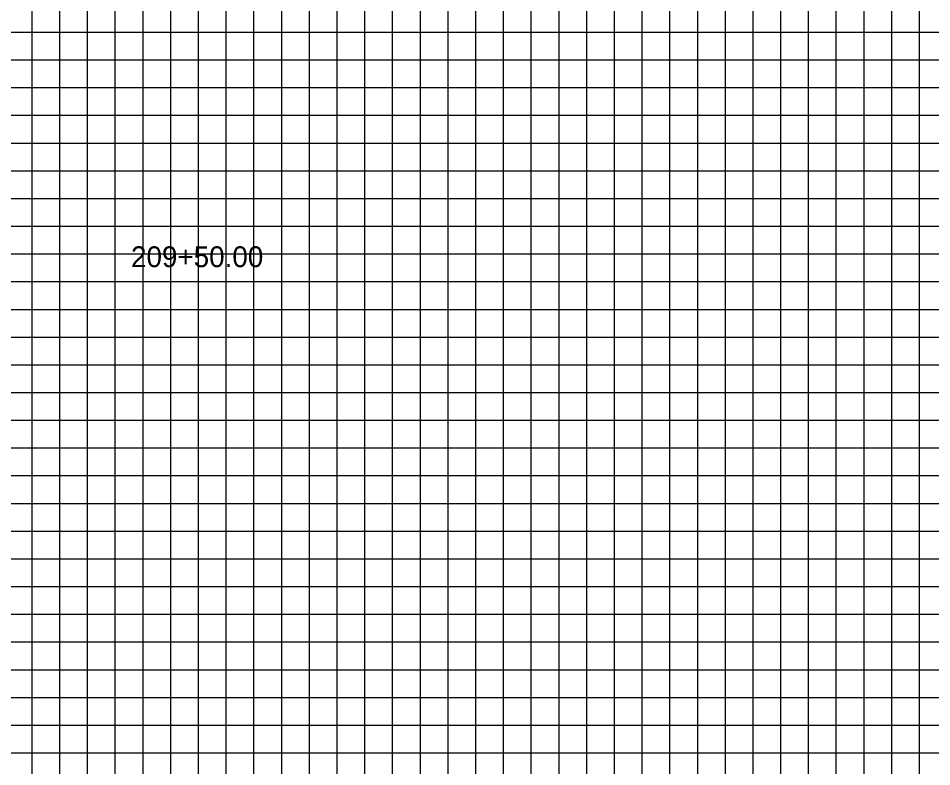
# Model space of a CAD drawing. Extents: x 967 to 1326, y 964 to 1744.
# Drawn here: x 1147 to 1212.9, y 1299 to 1353 of the extents above; entities that cross this region are included whole.
import ezdxf

# ---------------------------------------------------------------- set-up
doc = ezdxf.new("R2010")
doc.units = 0
for name, color, linetype in [('Default', 7, 'Continuous'), ('RD_XS_TX_Elev_PR', 7, 'Continuous'), ('RD_XS_TX_Slope', 7, 'Continuous')]:
    doc.layers.add(name, color=color, linetype=linetype)

msp = doc.modelspace()

# ---------------------------------------------------------------- linework, layer by layer
at = {"layer": 'RD_XS_TX_Elev_PR'}
for p, q in [((1150, 1280), (1150, 1450)), ((1160, 1280), (1160, 1450)), ((1170, 1280), (1170, 1450)), ((1180, 1280), (1180, 1450)), ((1190, 1280), (1190, 1450)), ((1200, 1280), (1200, 1450)), ((1210, 1280), (1210, 1450)), ((1000, 1350), (1320, 1350)), ((1000, 1340), (1320, 1340)), ((1000, 1330), (1320, 1330)), ((1000, 1320), (1320, 1320)), ((1000, 1310), (1320, 1310)), ((1000, 1300), (1320, 1300))]:
    msp.add_line(p, q, dxfattribs=at)
at = {"layer": 'RD_XS_TX_Slope'}
for p, q in [((1148, 1280), (1148, 1450)), ((1152, 1280), (1152, 1450)), ((1154, 1280), (1154, 1450)), ((1156, 1280), (1156, 1450)), ((1158, 1280), (1158, 1450)), ((1162, 1280), (1162, 1450)), ((1164, 1280), (1164, 1450)), ((1166, 1280), (1166, 1450)), ((1168, 1280), (1168, 1450)), ((1172, 1280), (1172, 1450)), ((1174, 1280), (1174, 1450)), ((1176, 1280), (1176, 1450)), ((1178, 1280), (1178, 1450)), ((1182, 1280), (1182, 1450)), ((1184, 1280), (1184, 1450)), ((1186, 1280), (1186, 1450)), ((1188, 1280), (1188, 1450)), ((1192, 1280), (1192, 1450)), ((1194, 1280), (1194, 1450)), ((1196, 1280), (1196, 1450)), ((1198, 1280), (1198, 1450)), ((1202, 1280), (1202, 1450)), ((1204, 1280), (1204, 1450)), ((1206, 1280), (1206, 1450)), ((1208, 1280), (1208, 1450)), ((1212, 1280), (1212, 1450)), ((1000, 1352), (1320, 1352)), ((1000, 1348), (1320, 1348)), ((1000, 1346), (1320, 1346)), ((1000, 1344), (1320, 1344)), ((1000, 1342), (1320, 1342)), ((1000, 1338), (1320, 1338)), ((1000, 1336), (1320, 1336)), ((1000, 1334), (1320, 1334)), ((1000, 1332), (1320, 1332)), ((1000, 1328), (1320, 1328)), ((1000, 1326), (1320, 1326)), ((1000, 1324), (1320, 1324)), ((1000, 1322), (1320, 1322)), ((1000, 1318), (1320, 1318)), ((1000, 1316), (1320, 1316)), ((1000, 1314), (1320, 1314)), ((1000, 1312), (1320, 1312)), ((1000, 1308), (1320, 1308)), ((1000, 1306), (1320, 1306)), ((1000, 1304), (1320, 1304)), ((1000, 1302), (1320, 1302))]:
    msp.add_line(p, q, dxfattribs=at)

# ---------------------------------------------------------------- texts
at = {"layer": 'Default'}
msp.add_text('209+50.00', height=1.5, dxfattribs=at).set_placement((1155.134, 1335.045))

doc.saveas('drawing.dxf')
